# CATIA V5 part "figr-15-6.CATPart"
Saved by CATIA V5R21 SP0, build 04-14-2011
Part number: Part1
Bounding box of the stored display mesh (mm): x -50 to 50, y -32.5 to 33.5, z -52 to 1
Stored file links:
  D:\CATIA V5R21 E-RESOURCES\CATIA-V5R21\catia-v5r21-prt\c15-catia-v5r20-prt\c15-catia-v5r21-figr-15-6.CATPart
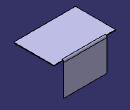
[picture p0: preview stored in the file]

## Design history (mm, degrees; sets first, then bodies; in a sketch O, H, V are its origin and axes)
SheetMetalParameters1: Thickness 1, BendRadius 2, KFactor 0.400515 {= log(min(100,max(20*SheetMetalParameters1.BendRadius,SheetMetalParameters1.Thickness)/SheetMetalParameters1.Thickness))/log(100)/2}, ReliefRadialLength 1, ReliefAxialLength 2, MinimumBendRadius 0
Body1 (main body)
  Sketch1 on xy-plane, origin (0, 0, 0), H (1, 0, 0), V (0, 1, 0)
    line L1 (-50, 32.5) -> (50, 32.5)
    line L2 (50, 32.5) -> (50, -32.5)
    line L3 (50, -32.5) -> (-50, -32.5)
    line L4 (-50, -32.5) -> (-50, 32.5)
    length L1 = 100
    length L2 = 65
    horizontal: L1 H, L3 H
    vertical: L2 V, L4 V
    symmetry: L4 L2 V, L1 L3 H
  Wall1: Thickness 1, Profile Sketch1
  d_NewWallOnEdge1: NewWallOnEdge_Edge edge [face of Wall1 | face of Wall1], KFacteur 0.400515 {= log(min(100,max(20*d_NewWallOnEdge1.Radius,SheetMetalParameters1.Thickness)/SheetMetalParameters1.Thickness))/log(100)/2}, NewWallOnEdge_Length 53, NewWallOnEdge_HeightLimitOffset 0, NewWallOnEdge_WidthOffset1 -15, NewWallOnEdge_WidthOffset2 -15, NewWallOnEdge_Angle 90, NewWallOnEdge_BendRadiusValue 2 {= SheetMetalParameters1.BendRadius}, NewWallOnEdge_BendTable SheetMetalParameters1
